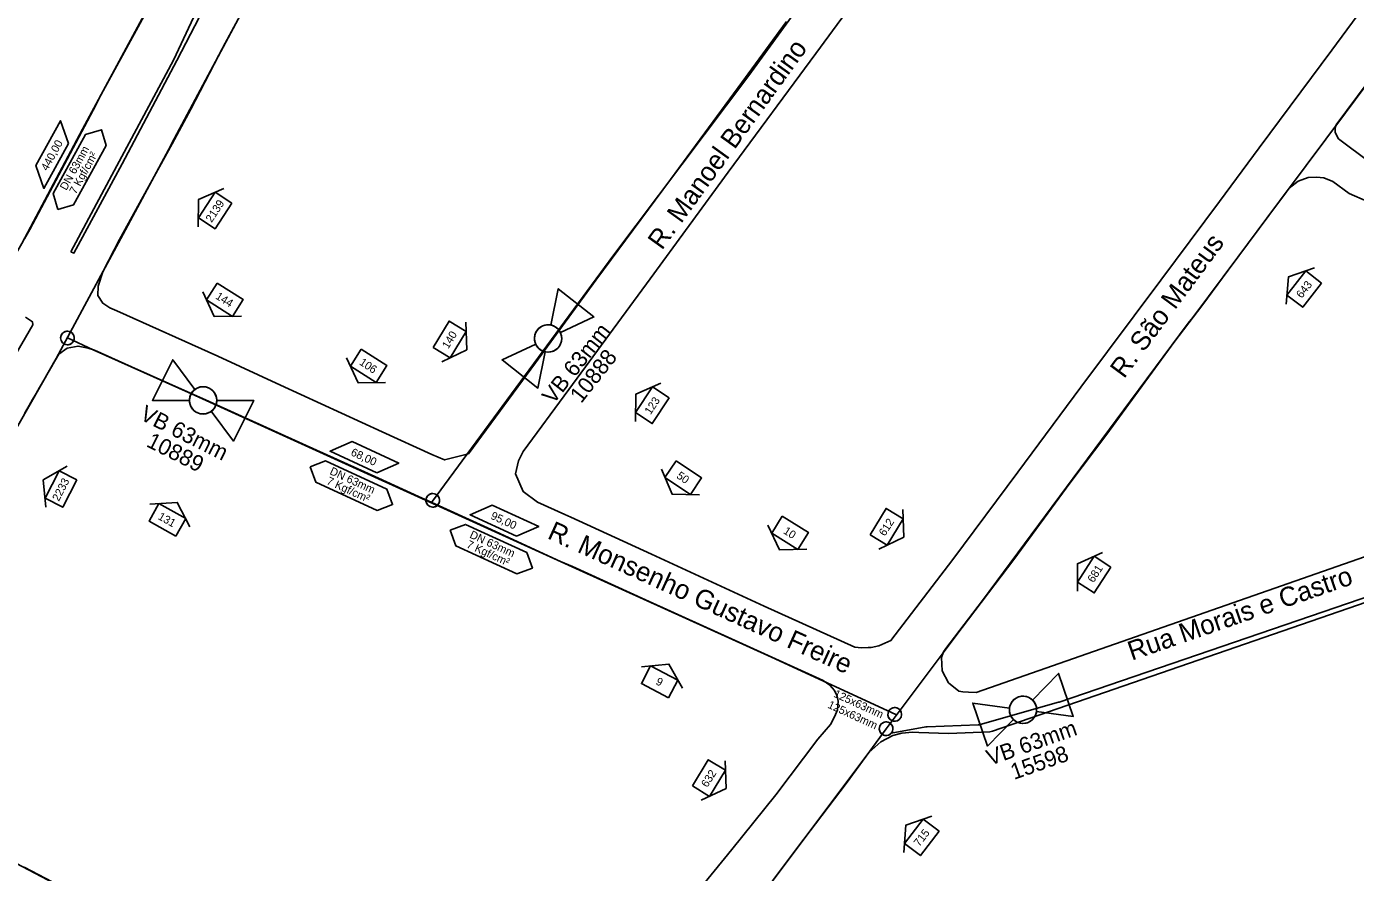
# Model space of a CAD drawing. Extents: x 656692 to 673945, y 7585994 to 7599066.
# Drawn here: x 669220.6 to 669718.8, y 7591240.2 to 7591557.3 of the extents above; entities that cross this region are included whole.
import ezdxf

# ---------------------------------------------------------------- set-up
doc = ezdxf.new("R2010")
doc.units = 0
for name, color, linetype in [('FORMATO', 7, 'Continuous'), ('LOGRADOURO', 7, 'Continuous'), ('LOGRADOURO_TEXTO', 7, 'Continuous'), ('NUM_REF', 7, 'Continuous'), ('SIMBOLO', 7, 'Continuous'), ('TEXTO', 7, 'Continuous'), ('TUBO_PEAD_GN_125', 7, 'Continuous'), ('TUBO_PEAD_GN_63', 7, 'Continuous'), ('VALVULA_PEAD_63', 7, 'Continuous')]:
    doc.layers.add(name, color=color, linetype=linetype)

# ---------------------------------------------------------------- blocks, each defined once
blk = doc.blocks.new('INTERLIGACAO_5')
at = {"layer": 'SIMBOLO'}
blk.add_circle((0, 0), 1.28, dxfattribs=at)
for start, end in [(0, 180), (180, 0)]:
    blk.add_arc((0, 0), 1.28, start, end, dxfattribs=at)
blk = doc.blocks.new('VALVULA_PEAD_DN_9')
at = {"layer": 'VALVULA_PEAD_63'}
for points in [[(-1.14, 0.57), (-4.25, 2.13), (-4.25, -2.13), (-1.14, -0.57)], [(-1.14, -0.57), (-4.25, -2.13), (-4.25, 2.13), (-1.14, 0.57)], [(1.14, -0.57), (4.25, -2.13), (4.25, 2.13), (1.14, 0.57)], [(1.14, -0.57), (4.25, -2.13), (4.25, 2.13), (1.14, 0.57)]]:
    blk.add_lwpolyline(points, dxfattribs=at)
blk.add_circle((0, 0), 1.28, dxfattribs=at)
for start, end in [(90, 270), (270, 90), (153.4349, 206.5651), (0, 26.5651), (333.4349, 0)]:
    blk.add_arc((0, 0), 1.28, start, end, dxfattribs=at)
blk = doc.blocks.new('NUM_REF_1')
at = {"layer": 'NUM_REF'}
blk.add_lwpolyline([(-4.3125, 0.9375), (0, 3.75), (4.3125, 0.9375)], dxfattribs=at)
blk.add_lwpolyline([(2.875, -1.875), (2.875, 1.875), (-2.875, 1.875), (-2.875, -1.875)], close=True, dxfattribs=at)
blk = doc.blocks.new('INTERLIGACAO_8')
at = {"layer": 'SIMBOLO'}
blk.add_circle((0, 0), 1.28, dxfattribs=at)
for start, end in [(0, 180), (180, 0)]:
    blk.add_arc((0, 0), 1.28, start, end, dxfattribs=at)
blk = doc.blocks.new('VALVULA_PEAD_DN_14')
at = {"layer": 'VALVULA_PEAD_63'}
for points in [[(-1.14, 0.57), (-4.25, 2.13), (-4.25, -2.13), (-1.14, -0.57)], [(-1.14, -0.57), (-4.25, -2.13), (-4.25, 2.13), (-1.14, 0.57)], [(1.14, -0.57), (4.25, -2.13), (4.25, 2.13), (1.14, 0.57)], [(1.14, -0.57), (4.25, -2.13), (4.25, 2.13), (1.14, 0.57)]]:
    blk.add_lwpolyline(points, dxfattribs=at)
blk.add_circle((0, 0), 1.28, dxfattribs=at)
for start, end in [(90, 270), (270, 90), (153.4349, 206.5651), (0, 26.5651), (333.4349, 0)]:
    blk.add_arc((0, 0), 1.28, start, end, dxfattribs=at)

msp = doc.modelspace()

# ---------------------------------------------------------------- linework, layer by layer
at = {"layer": 'LOGRADOURO'}
for p, q in [((669716.49, 7591494.69), (669723.39, 7591491.73)), ((669576.68, 7591307.6), (669758.4, 7591371.13)), ((669582.7, 7591293.15), (669768.46, 7591357.24)), ((669566.3, 7591292.23), (669581.79, 7591292.97))]:
    msp.add_line(p, q, dxfattribs=at)
for points in [[(670020.73, 7591711.24), (669917.25, 7591785.61), (669914.34, 7591787.62), (669911.92, 7591787.99), (669909.75, 7591786.89), (669903.7, 7591778.88), (669901.95, 7591776.55), (669874.21, 7591739.26), (669860.72, 7591720.96), (669859.46, 7591719.37), (669835.86, 7591687.6), (669820.72, 7591667.17), (669818.94, 7591664.69), (669816.97, 7591662.05), (669801.4, 7591641.37), (669781.34, 7591614.09), (669756, 7591580.23), (669711.62, 7591520.51), (669711.26, 7591519.36), (669711.3, 7591517.55), (669712.49, 7591515.28), (669724.35, 7591506.29)], [(669189.53, 7591673.97), (669223.09, 7591671.85), (669267.28, 7591669.21), (669269.69, 7591669.12), (669294.37, 7591667.49), (669297.43, 7591666.85), (669299.71, 7591665.59), (669300.96, 7591664.35), (669302.29, 7591661.82), (669303.15, 7591655.69), (669302.03, 7591643.79), (669297.61, 7591627.93), (669289.8, 7591609.29), (669273.43, 7591577.49), (669247.84, 7591530.44), (669246.69, 7591528.11), (669221.83, 7591481.25), (669219.83, 7591477.69)], [(669237.18, 7591472.91), (669238.3, 7591472.4), (669256.41, 7591505.89), (669276.89, 7591544.54), (669292.15, 7591574.14), (669304.82, 7591601.5), (669311.85, 7591620.43), (669322.45, 7591651.2), (669319.55, 7591652.25), (669309.38, 7591620.83), (669301.89, 7591602.24), (669290.79, 7591577.08), (669275.65, 7591544.75), (669254.37, 7591505.12), (669237.18, 7591472.91)], [(669313, 7591584.7), (669288.66, 7591539.12), (669274.95, 7591513.35), (669273.83, 7591511.13), (669255.86, 7591477.89), (669249.17, 7591465.34), (669247.36, 7591460.01), (669247.32, 7591456.46), (669249.21, 7591453.6), (669251.85, 7591451.87), (669254.39, 7591450.78), (669292.3, 7591433.69), (669315.79, 7591422.9), (669353.97, 7591405.36), (669372.54, 7591396.89), (669374.89, 7591395.93), (669377.33, 7591394.85), (669386.23, 7591397.1), (669411.35, 7591431.25), (669434.05, 7591462.2), (669461.96, 7591499.97), (669487.41, 7591534.49), (669505.53, 7591559.16)], [(669719.43, 7591561.36), (669709.96, 7591548.49), (669682.72, 7591511.79), (669667.82, 7591491.75), (669645.85, 7591462.28), (669615.92, 7591422.11), (669592.24, 7591390.26), (669567.94, 7591357.46), (669544.64, 7591327.11), (669540.1, 7591325.15), (669537.2, 7591324.52), (669536.17, 7591324.55), (669533.63, 7591324.37), (669531.18, 7591324.6), (669497.09, 7591340), (669454.86, 7591359.56), (669424.63, 7591373.45), (669422.38, 7591374.35), (669412.13, 7591378.99), (669406.74, 7591383.01), (669403.88, 7591389.59), (669405.03, 7591394.48), (669406.78, 7591397.96), (669423.9, 7591421.26), (669454.43, 7591462.8), (669483.69, 7591502.67), (669516.49, 7591547.19), (669543.69, 7591584.23)], [(669716.49, 7591494.69), (669710.41, 7591499.29), (669706.99, 7591500.65), (669704.26, 7591500.83), (669701.09, 7591500.68), (669697.41, 7591499.32), (669694, 7591496.68), (669675.12, 7591471.42), (669657.81, 7591448.23), (669656.12, 7591446.1), (669634.48, 7591416.99)], [(669220.12, 7591448.31), (669222.77, 7591446.65), (669222.9, 7591445.44), (669215.2, 7591432.17)], [(669394.81, 7591368.81), (669369.79, 7591380.12), (669367.48, 7591381.09), (669352.49, 7591388.06), (669324.09, 7591400.89), (669289.03, 7591416.75), (669259.87, 7591429.71), (669246.01, 7591435.94), (669243.69, 7591436.71), (669239.88, 7591437.51), (669235.75, 7591436.72), (669232.62, 7591434.44), (669231.4, 7591432.36), (669230.17, 7591430.28), (669209.43, 7591394.02)], [(669576.68, 7591307.6), (669573.77, 7591307.8), (669571.58, 7591307.97), (669570.11, 7591308.22), (669566.22, 7591311.31), (669563.85, 7591315.74), (669563.67, 7591320.82), (669564.35, 7591322.87), (669565.3, 7591324.12), (669566.92, 7591326.34), (669578.96, 7591342.13), (669610.52, 7591384.69), (669634.48, 7591416.99)], [(669452.68, 7591342.41), (669425.32, 7591354.86), (669420.81, 7591356.76), (669394.81, 7591368.81)], [(669453.58, 7591210.22), (669485.04, 7591248.78), (669501.47, 7591269.25), (669517.28, 7591290.15), (669522.03, 7591295.65), (669523.48, 7591298.51), (669524.65, 7591301.18), (669524.92, 7591304.41), (669524.52, 7591306.28), (669523.48, 7591308.47), (669521.78, 7591310.45), (669519.31, 7591312.1), (669486.23, 7591327.16), (669452.68, 7591342.41)], [(669548.77, 7591292.47), (669545.41, 7591291.52), (669540.88, 7591289.11), (669536.41, 7591285.11), (669518.37, 7591261.19), (669500.55, 7591237.3), (669476.8, 7591205.89), (669440.06, 7591172.57), (669409.69, 7591146.07), (669365.28, 7591107.23), (669330.81, 7591077.32), (669299.7, 7591050.16), (669297.89, 7591048.38), (669296.26, 7591045.28), (669295.9, 7591027.58)], [(669566.3, 7591292.23), (669555.14, 7591292.66), (669552.78, 7591292.78), (669548.77, 7591292.47)], [(669219.62, 7591242.17), (669266.65, 7591217.53)]]:
    msp.add_lwpolyline(points, dxfattribs=at)
msp.add_arc((669581.63, 7591296.25), 3.28, 272.7548, 289.0364, dxfattribs=at)
at = {"layer": 'SIMBOLO'}
for points in [[(669236.29, 7591513.52), (669227.06, 7591496.66), (669224.02, 7591505.17), (669233.25, 7591522.02)], [(669351.86, 7591390.05), (669334.4, 7591398.09), (669342.67, 7591401.71), (669360.13, 7591393.67)], [(669404.31, 7591366.24), (669386.85, 7591374.27), (669395.13, 7591377.9), (669412.59, 7591369.86)]]:
    msp.add_lwpolyline(points, close=True, dxfattribs=at)
for points in [[(669232.29, 7591488.79), (669230.56, 7591494.73), (669242.68, 7591516.87), (669248.62, 7591518.61), (669250.36, 7591512.67), (669238.23, 7591490.53), (669232.29, 7591488.79)], [(669326.91, 7591392.31), (669332.71, 7591394.46), (669355.65, 7591383.9), (669357.8, 7591378.1), (669351.99, 7591375.95), (669329.05, 7591386.51), (669326.91, 7591392.31)], [(669379.36, 7591368.5), (669385.17, 7591370.65), (669408.11, 7591360.09), (669410.25, 7591354.29), (669404.45, 7591352.14), (669381.51, 7591362.7), (669379.36, 7591368.5)]]:
    msp.add_lwpolyline(points, dxfattribs=at)
at = {"layer": 'TUBO_PEAD_GN_125'}
msp.add_lwpolyline([(669491.11, 7591224.8), (669509.65, 7591249.55), (669527.84, 7591273.5), (669542.86, 7591294.06), (669571.32, 7591331.99), (669590.75, 7591357.54), (669611.78, 7591386.12), (669625.67, 7591404.53), (669637.53, 7591420.81), (669651.09, 7591439.33), (669661.26, 7591452.56), (669671.09, 7591466.01), (669685.66, 7591485.54), (669715.12, 7591524.92), (669730.39, 7591545.41)], dxfattribs=at)
at = {"layer": 'TUBO_PEAD_GN_63'}
for p, q in [((669607.71, 7591304.04), (669763.14, 7591357.21)), ((669578.12, 7591295.62), (669607.55, 7591303.99)), ((669544.81, 7591292.41), (669557.79, 7591294.76)), ((669558.26, 7591294.81), (669577.34, 7591295.49))]:
    msp.add_line(p, q, dxfattribs=at)
for points in [[(669372.41, 7591378.95), (669440.83, 7591471.78), (669491.4, 7591538.96), (669564.79, 7591639.92), (669581.08, 7591669.47), (669582.24, 7591675.44), (669582.19, 7591685.82), (669582.07, 7591702.02), (669581.98, 7591707.32), (669580.39, 7591734.51), (669579.47, 7591737.43), (669574.48, 7591745.26), (669568.84, 7591754.26), (669565.08, 7591760.62), (669556.55, 7591770.19), (669543.73, 7591779.29), (669535.72, 7591781.72), (669524.61, 7591781.07)], [(669312.18, 7591677.38), (669302.77, 7591654.72), (669300.81, 7591640.82), (669297.08, 7591625.85), (669291.69, 7591614.21), (669285.88, 7591601.69), (669278.3, 7591586.9), (669263.07, 7591558.77), (669241.51, 7591518.79), (669218.84, 7591476.04), (669140.27, 7591338.73), (669085.61, 7591243.17), (669035.71, 7591157.47), (669005.97, 7591103.03), (668966.34, 7591053.81), (668948.49, 7591034.4), (668935.65, 7591021.83), (668916.48, 7591003.66), (668900.75, 7590989.83), (668884.13, 7590976.88), (668863.91, 7590962.18), (668847.67, 7590951.49)], [(669298.98, 7591558.45), (669298.25, 7591557.08), (669297.4, 7591555.49), (669296.64, 7591554.06), (669295.76, 7591552.41), (669294.43, 7591549.95), (669293.9, 7591548.98), (669293.29, 7591547.83), (669292.66, 7591546.58), (669282.12, 7591526.36), (669275.11, 7591513.41), (669264.3, 7591493.56), (669255.46, 7591477.51), (669249.31, 7591465.61), (669231.72, 7591432.83), (669230.82, 7591431.4), (669229.87, 7591429.77), (669228.66, 7591427.61), (669227.03, 7591424.8), (669225.47, 7591422.04), (669224.19, 7591419.8), (669222.86, 7591417.45), (669221.57, 7591415.25), (669219.85, 7591412.24)], [(669546.52, 7591299.46), (669499.84, 7591320.85), (669427.88, 7591353.56), (669282.46, 7591419.6), (669245.6, 7591436.1), (669235.91, 7591440.56)], [(669407.23, 7591144.17), (669378.38, 7591158.68), (669377.21, 7591159.29), (669372.07, 7591161.96), (669365.87, 7591165.18), (669301.77, 7591198.83), (669164.62, 7591270.87), (669145.57, 7591281.26)]]:
    msp.add_lwpolyline(points, dxfattribs=at)
for centre, start, end in [((669606.65, 7591307.14), 285.8772, 288.8863), ((669558.37, 7591291.53), 92.0478, 100.2588), ((669577.22, 7591298.77), 272.0478, 285.8772)]:
    msp.add_arc(centre, 3.28, start, end, dxfattribs=at)

# ---------------------------------------------------------------- block references
at = {"layer": 'FORMATO'}
for p, xscale, yscale, rotation in [((669291.29, 7591488.36), 2.0000000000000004, 2, 56.41810306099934), ((669699.65, 7591458.91), 2.0000000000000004, 1.9999999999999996, 52.3798521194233), ((669294.92, 7591454.91), 2, 2, 147.77720462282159), ((669379.2, 7591440.03), 2, 2, -121.23446205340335), ((669348.85, 7591430.1), 2, 2, 147.77720462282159), ((669455.22, 7591415.35), 2.0000000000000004, 2, 56.41810306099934), ((669466.8, 7591388.18), 2, 2, 146.13346663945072), ((669233.47, 7591383.94), 2, 2, 62.75069825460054), ((669273.38, 7591372.39), 1.9999999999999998, 2.0000000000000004, -29.3859733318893), ((669543.05, 7591369.8), 2, 2, -121.23446205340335), ((669506.84, 7591367.51), 1.9999999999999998, 2.0000000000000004, 148.27870106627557), ((669620.89, 7591351.85), 1.9999999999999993, 1.9999999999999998, 57.133290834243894), ((669457.95, 7591311.65), 2, 2, -27.502111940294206), ((669476.42, 7591275.59), 2, 2, -121.23446205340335), ((669556.25, 7591253.36), 2.0000000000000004, 1.9999999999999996, 52.3798521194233)]:
    msp.add_blockref('NUM_REF_1', p, dxfattribs=dict(at, xscale=xscale, yscale=yscale, rotation=rotation))
at = {"layer": 'SIMBOLO'}
for name, p, xscale, yscale, rotation in [('INTERLIGACAO_5', (669235.91, 7591440.56), 1.9999999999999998, 2.0000000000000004, 32.01506894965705), ('INTERLIGACAO_5', (669372.87, 7591379.7), 1.9999999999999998, 2.0000000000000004, 32.01506894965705), ('INTERLIGACAO_5', (669546.1, 7591299.43), 2, 2, -40.263999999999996), ('INTERLIGACAO_8', (669542.86, 7591294.06), 2, 1.9999999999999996, -40.263999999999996)]:
    msp.add_blockref(name, p, dxfattribs=dict(at, xscale=xscale, yscale=yscale, rotation=rotation))
at = {"layer": 'VALVULA_PEAD_63'}
for name, p, xscale, yscale, rotation in [('VALVULA_PEAD_DN_9', (669416.11, 7591440.4), 3.9999999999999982, 3.9999999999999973, 51.766118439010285), ('VALVULA_PEAD_DN_9', (669286.75, 7591417.18), 3.9999999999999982, 3.9999999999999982, -26.644788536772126), ('VALVULA_PEAD_DN_14', (669594.19, 7591301.18), 3.999999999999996, 3.9999999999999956, 19.085574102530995)]:
    msp.add_blockref(name, p, dxfattribs=dict(at, xscale=xscale, yscale=yscale, rotation=rotation))

# ---------------------------------------------------------------- texts
for s, height, rotation, p in [('2139', 3, 56.4181, (669289.97, 7591483.65)), ('643', 3, 52.3799, (669698.71, 7591455.23)), ('144', 3, 327.7772, (669291.16, 7591455.5)), ('140', 3, 58.7655, (669378.67, 7591436.26)), ('VB 63mm', 6, 51.7661, (669418.07, 7591415.42)), ('10888', 6, 51.7661, (669428.53, 7591415.77)), ('106', 3, 326.2729, (669345.11, 7591430.79)), ('123', 3, 56.4181, (669454.54, 7591411.61)), ('VB 63mm', 6, 333.3552, (669262.68, 7591410.23)), ('10889', 6, 333.3552, (669265.13, 7591400.06)), ('2233', 3, 62.7507, (669232.67, 7591379.11)), ('50', 3, 324.6291, (669464.04, 7591388.3)), ('131', 3, 330.614, (669269.6, 7591372.79)), ('612', 3, 57.2612, (669542.42, 7591366.05)), ('10', 3, 326.7744, (669504.07, 7591367.53)), ('681', 3, 57.1333, (669620.63, 7591348.61)), ('9', 3, 332.4979, (669456.22, 7591310.86)), ('125x63mm', 3, 335.3925, (669522.97, 7591306.14)), ('125x63mm', 3, 335.3925, (669520.73, 7591302.03)), ('VB 63mm', 6, 19.4541, (669581.77, 7591280.16)), ('15598', 6, 19.4541, (669590.8, 7591274.87)), ('632', 3, 57.2612, (669475.79, 7591271.84)), ('715', 3, 52.3799, (669555.31, 7591249.68))]:
    msp.add_text(s, height=height, rotation=rotation).set_placement(p)
at = {"layer": 'LOGRADOURO_TEXTO'}
for s, rotation, p in [('R. Manoel Bernardino', 54.1984, (669458.8, 7591473.21)), ('R. São Mateus', 53.5247, (669632.08, 7591425.04)), ('R. Monsenho Gustavo Freire', 335.5784, (669415.47, 7591365.57)), ('Rua Morais e Castro', 19.0834, (669634.96, 7591319.56))]:
    msp.add_text(s, height=7.2, rotation=rotation, dxfattribs=at).set_placement(p)
at = {"layer": 'TEXTO'}
for s, rotation, p in [('440,00', 61.2952, (669228.39, 7591503)), ('DN 63mm', 61.2952, (669235.49, 7591495.67)), ('7 Kgf/cm²', 61.2952, (669239.05, 7591494.25)), ('68,00', 335.2863, (669341.88, 7591396.71)), ('DN 63mm', 335.2863, (669333.99, 7591389.6)), ('7 Kgf/cm²', 335.2863, (669332.83, 7591385.96)), ('95,00', 335.2863, (669394.33, 7591372.9)), ('DN 63mm', 335.2863, (669386.45, 7591365.79)), ('7 Kgf/cm²', 335.2863, (669385.28, 7591362.15))]:
    msp.add_text(s, height=3, rotation=rotation, dxfattribs=at).set_placement(p)

doc.saveas('drawing.dxf')
